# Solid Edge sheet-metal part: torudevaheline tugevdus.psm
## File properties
Title: torudevaheline tugevdus
Author: Stella-Marii
Template: Iso Metric Sheet Metal.psm
Last saved by: Stella-Marii
Revision: 6
Application: Solid Edge
Document Number: 40
Density: 7833,000 kg/m^3
Accuracy: 0,990
Material Thickness: 3,00 mm
Bend Radius: 1,00 mm
Relief Width: 1,00 mm
Relief Length: 0,00 mm
Neutral Factor: 0,330
Minimum Arc Length: 0,10 mm
Deviational Tolerance: 0,10 mm
Username: Stella-Marii
Material: Steel, structural
Face Style: Steel
Fill Style: ANSI32(Steel)
Virtual Style: Brushed steel
Grouping: Metals\Steel
LibraryName: Materials
Coef. of Thermal Exp: 1.3e-05
Thermal Conductivity: 32.0
Specific Heat: 481.0
Modulus of Elasticity: 199947953000.0
Poisson's Ratio: 0.29
Yield Stress: 262000766.0
Ultimate Stress: 358527364.0
Elongation: 0.0
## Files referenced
C:\Users\Stella-Marii\DATA\KOOL\Solid Edge - scooter\raami alumine toru.par
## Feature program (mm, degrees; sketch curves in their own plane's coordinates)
base tab "unnamed BaseTab 1"
sheet metal cutout "SheetMetalCutout_1"
sheet metal cutout "SheetMetalCutout_2"
sheet metal cutout "SheetMetalCutout_3"
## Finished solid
Body 1: solid body, 10 faces, 24 edges, 16 vertices.
  Faces by surface: plane 8, cylinder 2
  Edges by curve: line 20, circle 4
Bounding box of the edges (mm): 84.466 x 3.000 x 94.154, from (-52.3826, 0, -6.7943) to (32.0829, 3, 87.3601).
Cylindrical faces by radius (mm): R14.8961 x1, R84.2608 x1
Planar faces by outward normal: +y 1, +z 1, -y 1, oblique 5
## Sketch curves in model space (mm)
line (13.4527, 0, 41.7496) -> (32.0829, 0, 46.8139)
arc centre (19.933, 0, 28.3369) radius 14.8961 from (7.2194, 0, 20.5744) through (5.6432, 0, 32.5435) to (13.4527, 0, 41.7496)
line (-37.6059, 0, -6.7943) -> (7.2194, 0, 20.5744)
line (-52.3826, 0, 0.9689) -> (-37.6059, 0, -6.7943)
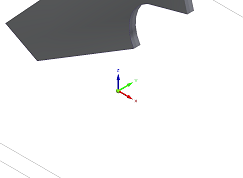
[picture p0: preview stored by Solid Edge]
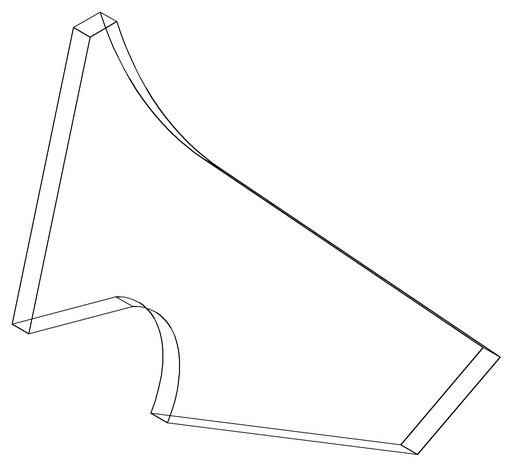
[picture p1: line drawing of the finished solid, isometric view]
